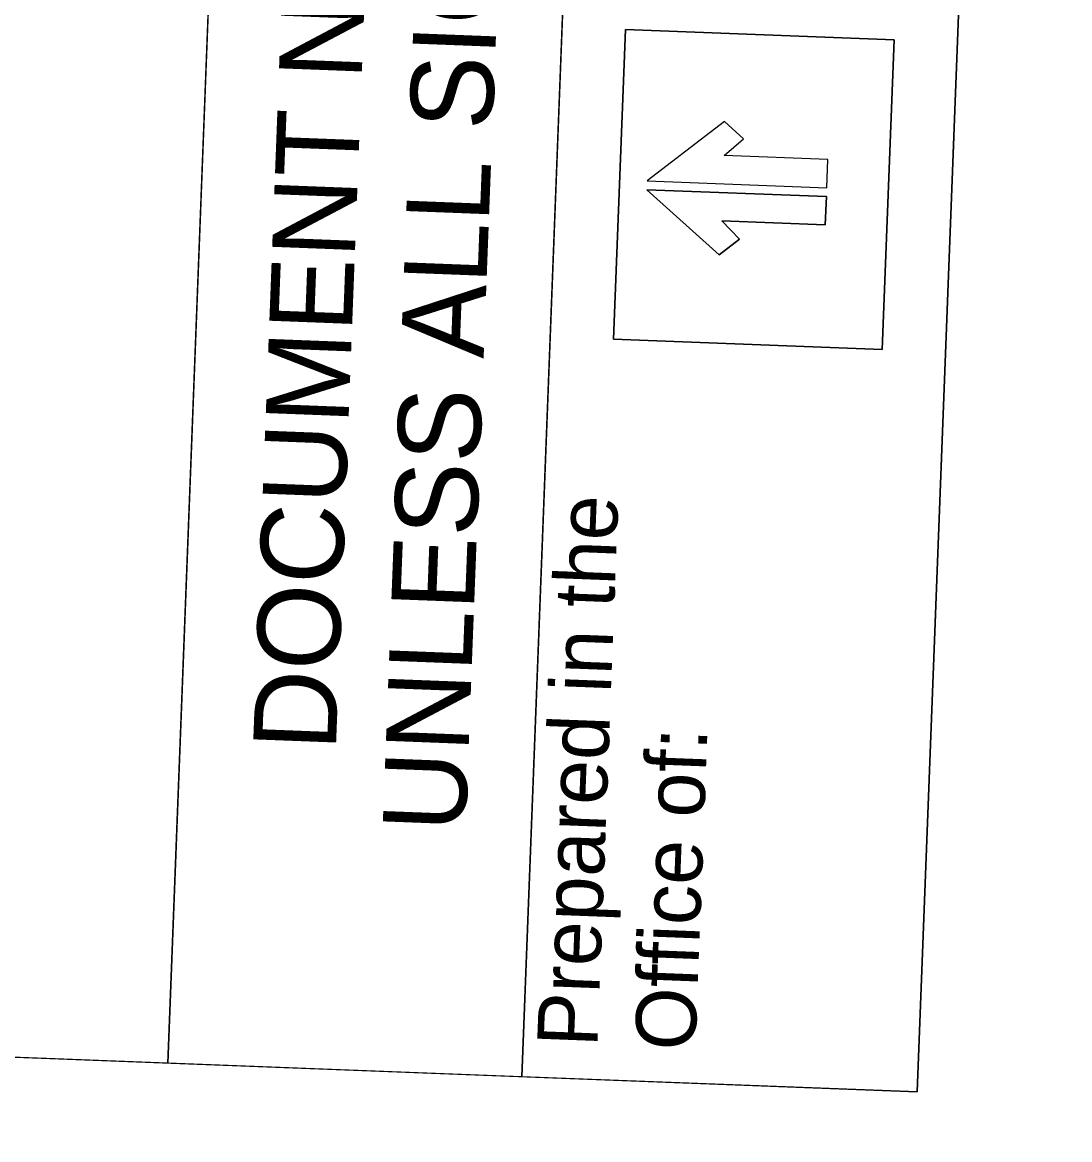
# Model space of a CAD drawing. Extents: x 2093420 to 2100301, y 676254 to 688367.
# Drawn here: x 2097353.1 to 2097418, y 687978 to 688047.2 of the extents above; entities that cross this region are included whole.
import ezdxf

# ---------------------------------------------------------------- set-up
doc = ezdxf.new("R2010")
doc.units = 0
for name, color, linetype in [('Old_Level_2', 7, 'Continuous'), ('Scratch_Level_2', 7, 'Continuous'), ('Sheet Block Title CELL', 7, 'Continuous'), ('Sheet Layout Plan Border', 7, 'Continuous'), ('Sheet Sticker Exception Certification CELL', 7, 'Continuous')]:
    doc.layers.add(name, color=color, linetype=linetype)

msp = doc.modelspace()

# ---------------------------------------------------------------- linework, layer by layer
at = {"layer": 'Old_Level_2'}
msp.add_lwpolyline([(2097250.844, 687986.989), (2097258.012, 688173.798), (2097369.308, 688169.527), (2097362.14, 687982.718)], close=True, dxfattribs=at)
msp.add_lwpolyline([(2097250.844, 687986.989), (2097258.012, 688173.798), (2097369.308, 688169.527), (2097362.14, 687982.718)], close=True, dxfattribs=at)
at = {"layer": 'Scratch_Level_2'}
msp.add_lwpolyline([(2098179.191, 686705.436), (2097129.589, 686735.949), (2097169.498, 687776.569), (2097177.901, 687989.788), (2097203.71, 687988.798), (2097408.557, 687980.937), (2097412.418, 688081.546), (2098157.977, 688052.952), (2098148.298, 687800.707), (2098221.089, 687797.913)], close=True, dxfattribs=at)
at = {"layer": 'Sheet Block Title CELL'}
for points in [[(2097384.064, 687981.877), (2097391.226, 688168.503), (2097415.719, 688167.563), (2097408.557, 687980.937)], [(2097389.746, 688027.533), (2097390.482, 688046.71), (2097407.127, 688046.071), (2097406.391, 688026.894)], [(2097391.827, 688037.336), (2097402.957, 688036.909), (2097403.024, 688038.662), (2097396.605, 688038.909), (2097397.796, 688039.95), (2097396.615, 688041.018)]]:
    msp.add_lwpolyline(points, close=True, dxfattribs=at)
for points in [[(2097390.482, 688046.71), (2097389.746, 688027.533), (2097406.391, 688026.894), (2097407.127, 688046.071), (2097390.482, 688046.71)], [(2097391.827, 688037.336), (2097402.957, 688036.909), (2097403.024, 688038.662), (2097396.605, 688038.909), (2097397.796, 688039.95), (2097396.615, 688041.018), (2097391.827, 688037.336)], [(2097391.807, 688036.796), (2097402.936, 688036.369), (2097402.869, 688034.616), (2097396.449, 688034.863), (2097397.557, 688033.733), (2097396.298, 688032.759), (2097391.807, 688036.796)], [(2097396.298, 688032.759), (2097397.557, 688033.733), (2097396.449, 688034.863), (2097402.869, 688034.616), (2097402.936, 688036.369), (2097391.807, 688036.796), (2097396.298, 688032.759)]]:
    msp.add_lwpolyline(points, dxfattribs=at)
at = {"layer": 'Sheet Layout Plan Border'}
msp.add_lwpolyline([(2098179.191, 686705.436), (2097129.589, 686735.949), (2097169.498, 687776.569), (2097177.901, 687989.788), (2097203.71, 687988.798), (2097408.557, 687980.937), (2097412.418, 688081.546), (2098157.977, 688052.952), (2098148.298, 687800.707), (2098221.089, 687797.913)], close=True, dxfattribs=at)
at = {"layer": 'Sheet Sticker Exception Certification CELL'}
for p, q in [((2097362.14, 687982.718), (2097369.301, 688169.345)), ((2097362.14, 687982.718), (2097369.301, 688169.345)), ((2097391.226, 688168.503), (2097384.064, 687981.877)), ((2097391.226, 688168.503), (2097384.064, 687981.877)), ((2097384.064, 687981.877), (2097362.14, 687982.718)), ((2097384.064, 687981.877), (2097362.14, 687982.718))]:
    msp.add_line(p, q, dxfattribs=at)

# ---------------------------------------------------------------- texts
at = {"layer": 'Sheet Block Title CELL'}
for s, height, p in [('Prepared in the ', 3.73527, (2097388.743, 687983.68)), ('Office of:', 3.7353, (2097394.808, 687983.448))]:
    msp.add_text(s, height=height, rotation=87.80253, dxfattribs=at).set_placement(p)
at = {"layer": 'Sheet Sticker Exception Certification CELL'}
for s, p in [('UNLESS ALL SIGNATURES COMPLETED', (2097380.574, 687996.96)), ('UNLESS ALL SIGNATURES COMPLETED', (2097380.574, 687996.96)), ('DOCUMENT NOT CONSIDERED FINAL', (2097372.546, 688002.006)), ('DOCUMENT NOT CONSIDERED FINAL', (2097372.546, 688002.006))]:
    msp.add_text(s, height=5.13504, rotation=87.80253, dxfattribs=at).set_placement(p)

doc.saveas('drawing.dxf')
